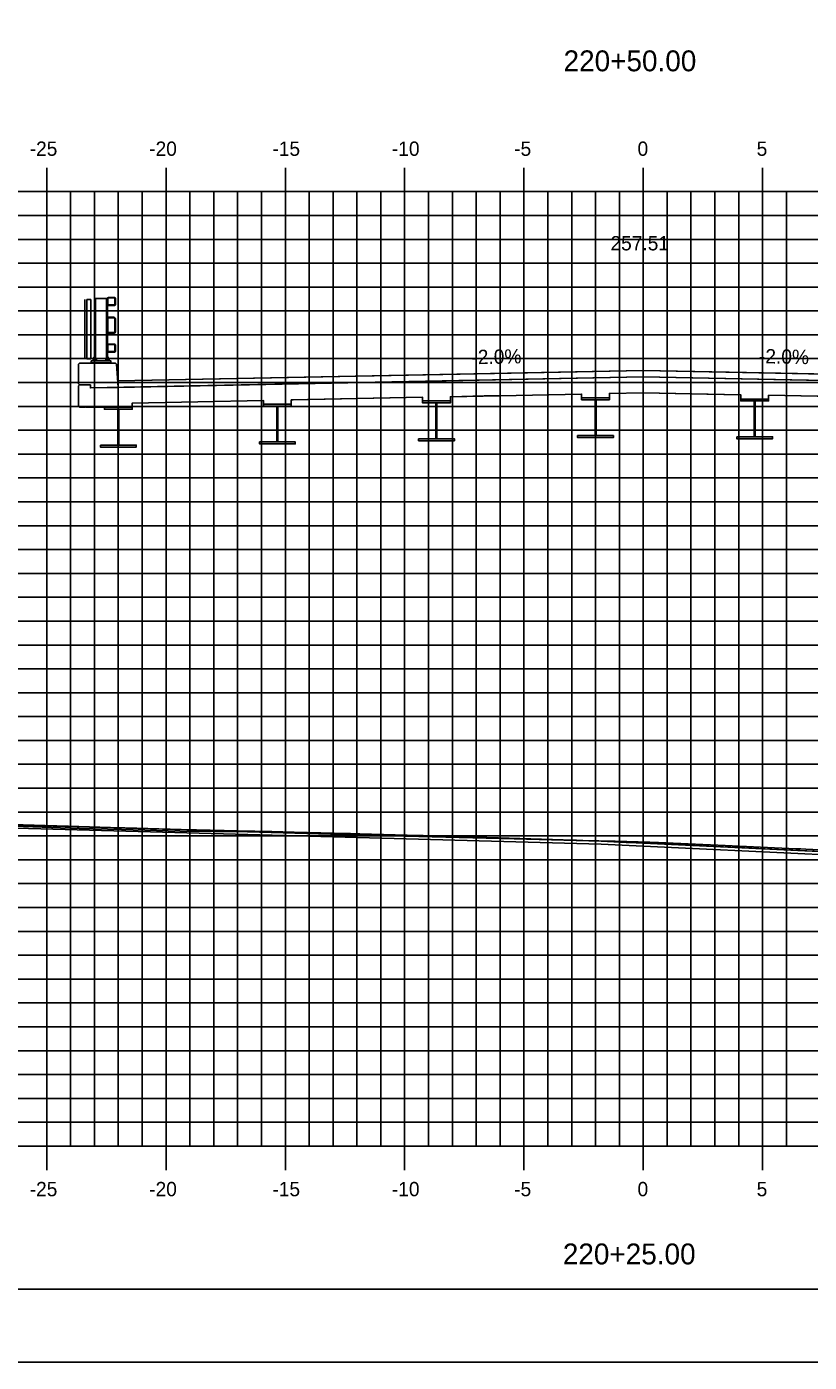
# Model space of a CAD drawing. Extents: x -22 to 1480, y -1511 to 8.
# Drawn here: x 700.4 to 733.2, y -184.5 to -128.6 of the extents above; entities that cross this region are included whole.
import ezdxf

# ---------------------------------------------------------------- set-up
doc = ezdxf.new("R2010")
doc.units = 0
for name, color, linetype in [('ANNOTATION', 7, 'Continuous'), ('BORDER', 7, 'Continuous'), ('D_Bridge_Deck', 7, 'Continuous'), ('D_Bridge_Railing', 7, 'Continuous'), ('D_Bridge_Superstructure', 7, 'Continuous'), ('D_Bridge_Superstructure_Slab', 7, 'Continuous'), ('D_Roadway_Centerline', 7, 'Continuous'), ('D_Roadway_Centerline_Text', 7, 'Continuous'), ('D_Roadway_Edge_TW', 7, 'Continuous'), ('H_V ANNOTATION', 7, 'Continuous'), ('MAJOR', 7, 'Continuous'), ('MINOR', 7, 'Continuous'), ('PLOT BOUNDARY', 7, 'Continuous'), ('S_Roadway_Centerline', 7, 'Continuous')]:
    doc.layers.add(name, color=color, linetype=linetype)

msp = doc.modelspace()

# ---------------------------------------------------------------- linework, layer by layer
at = {"layer": 'BORDER'}
msp.add_line((651.209, -181.466), (811.209, -181.466), dxfattribs=at)
at = {"layer": 'D_Bridge_Deck'}
for p, q in [((703.042, -143.569), (702.584, -143.569)), ((703.042, -143.694), (703.042, -143.569))]:
    msp.add_line(p, q, dxfattribs=at)
for points in [[(702.584, -143.569), (702.542, -143.527), (702.542, -142.691), (702.584, -142.65), (704.084, -142.65), (704.129, -142.691), (704.209, -143.67)], [(702.834, -144.504), (703.542, -144.504)]]:
    msp.add_lwpolyline(points, dxfattribs=at)
at = {"layer": 'D_Bridge_Railing'}
for p, q in [((703.792, -139.9), (704.042, -139.9)), ((703.792, -139.92), (704.042, -139.92)), ((702.886, -139.983), (702.886, -142.474)), ((703.052, -139.983), (702.886, -139.983)), ((703.052, -139.983), (703.052, -142.474)), ((703.257, -139.941), (703.257, -142.473)), ((703.712, -139.941), (703.712, -142.473)), ((703.751, -140.191), (703.751, -139.941)), ((703.771, -140.191), (703.771, -139.941)), ((704.042, -140.212), (703.792, -140.212)), ((704.042, -140.233), (703.792, -140.233)), ((704.063, -139.941), (704.063, -140.191)), ((704.084, -139.941), (704.084, -140.191)), ((703.751, -140.785), (703.751, -141.348)), ((703.776, -140.785), (703.776, -141.348)), ((704.032, -140.733), (703.802, -140.733)), ((704.032, -140.759), (703.802, -140.759)), ((704.058, -141.348), (704.058, -140.785)), ((704.084, -141.348), (704.084, -140.785)), ((703.802, -141.374), (704.032, -141.374)), ((703.802, -141.4), (704.032, -141.4)), ((703.751, -142.15), (703.751, -141.9)), ((703.771, -142.15), (703.771, -141.9)), ((703.792, -141.858), (704.042, -141.858)), ((703.792, -141.879), (704.042, -141.879)), ((704.063, -141.9), (704.063, -142.15)), ((704.084, -141.9), (704.084, -142.15)), ((703.052, -142.474), (702.886, -142.474)), ((703.183, -142.399), (703.256, -142.399)), ((703.183, -142.408), (703.256, -142.408)), ((703.183, -142.416), (703.256, -142.416)), ((703.183, -142.424), (703.256, -142.424)), ((703.183, -142.433), (703.256, -142.433)), ((703.183, -142.441), (703.256, -142.441)), ((703.183, -142.449), (703.256, -142.449)), ((703.183, -142.457), (703.256, -142.457)), ((703.183, -142.466), (703.256, -142.466)), ((703.185, -142.481), (703.185, -142.537)), ((703.201, -142.404), (703.237, -142.404)), ((703.201, -142.412), (703.237, -142.412)), ((703.201, -142.42), (703.237, -142.42)), ((703.201, -142.428), (703.237, -142.428)), ((703.201, -142.437), (703.237, -142.437)), ((703.201, -142.445), (703.237, -142.445)), ((703.201, -142.453), (703.237, -142.453)), ((703.201, -142.462), (703.237, -142.462)), ((703.201, -142.47), (703.237, -142.47)), ((703.254, -142.481), (703.254, -142.537)), ((703.714, -142.399), (703.787, -142.399)), ((703.714, -142.408), (703.787, -142.408)), ((703.714, -142.416), (703.787, -142.416)), ((703.714, -142.424), (703.787, -142.424)), ((703.714, -142.433), (703.787, -142.433)), ((703.714, -142.441), (703.787, -142.441)), ((703.714, -142.449), (703.787, -142.449)), ((703.714, -142.457), (703.787, -142.457)), ((703.714, -142.466), (703.787, -142.466)), ((703.716, -142.481), (703.716, -142.537)), ((703.732, -142.404), (703.769, -142.404)), ((703.732, -142.412), (703.769, -142.412)), ((703.732, -142.42), (703.769, -142.42)), ((703.732, -142.428), (703.769, -142.428)), ((703.732, -142.437), (703.769, -142.437)), ((703.732, -142.445), (703.769, -142.445)), ((703.732, -142.453), (703.769, -142.453)), ((703.732, -142.462), (703.769, -142.462)), ((703.732, -142.47), (703.769, -142.47)), ((703.785, -142.481), (703.785, -142.537)), ((704.042, -142.17), (703.792, -142.17)), ((704.042, -142.191), (703.792, -142.191))]:
    msp.add_line(p, q, dxfattribs=at)
for points in [[(702.802, -139.983), (702.802, -142.474)], [(703.219, -142.391), (703.219, -139.941), (703.751, -139.941), (703.751, -142.391)], [(703.183, -142.473), (703.183, -142.399), (703.191, -142.391), (703.247, -142.391), (703.256, -142.399), (703.256, -142.473)], [(703.714, -142.473), (703.714, -142.399), (703.722, -142.391), (703.779, -142.391), (703.787, -142.399), (703.787, -142.473)]]:
    msp.add_lwpolyline(points, dxfattribs=at)
for points in [[(703.075, -142.558), (703.895, -142.558), (703.895, -142.64), (703.075, -142.64)], [(703.075, -142.64), (703.895, -142.64), (703.895, -142.65), (703.075, -142.65)], [(703.146, -142.558), (703.292, -142.558), (703.292, -142.545), (703.146, -142.545)], [(703.15, -142.481), (703.164, -142.473), (703.274, -142.473), (703.288, -142.481), (703.288, -142.537), (703.274, -142.545), (703.164, -142.545), (703.15, -142.537)], [(703.678, -142.558), (703.823, -142.558), (703.823, -142.545), (703.678, -142.545)], [(703.682, -142.481), (703.695, -142.473), (703.806, -142.473), (703.819, -142.481), (703.819, -142.537), (703.806, -142.545), (703.695, -142.545), (703.682, -142.537)]]:
    msp.add_lwpolyline(points, close=True, dxfattribs=at)
for centre, radius, start, end in [((703.792, -139.941), 0.0417, 90, 180), ((703.792, -139.941), 0.0208, 90, 180), ((704.042, -139.941), 0.0417, 0, 90), ((704.042, -139.941), 0.0208, 0, 90), ((703.792, -140.191), 0.0417, 180, 270), ((703.792, -140.191), 0.0208, 180, 270), ((704.042, -140.191), 0.0417, 270, 0), ((704.042, -140.191), 0.0208, 270, 0), ((703.802, -140.785), 0.052, 90, 180), ((703.802, -140.785), 0.026, 90, 180), ((704.032, -140.785), 0.052, 0, 90), ((704.032, -140.785), 0.026, 0, 90), ((703.802, -141.348), 0.052, 180, 270), ((703.802, -141.348), 0.026, 180, 270), ((704.032, -141.348), 0.052, 270, 0), ((704.032, -141.348), 0.026, 270, 0), ((703.792, -141.9), 0.0417, 90, 180), ((703.792, -142.15), 0.0417, 180, 270), ((703.792, -141.9), 0.0208, 90, 180), ((703.792, -142.15), 0.0208, 180, 270), ((704.042, -141.9), 0.0417, 0, 90), ((704.042, -141.9), 0.0208, 0, 90), ((704.042, -142.15), 0.0417, 270, 0), ((704.042, -142.15), 0.0208, 270, 0), ((703.168, -142.506), 0.0302, 55.4339, 120), ((703.168, -142.512), 0.0302, 240, 304.5661), ((703.219, -142.59), 0.114, 72.412, 107.588), ((703.219, -142.428), 0.114, 252.412, 287.588), ((703.271, -142.506), 0.0302, 60, 124.5661), ((703.271, -142.512), 0.0302, 235.4339, 300), ((703.699, -142.506), 0.0302, 55.4339, 120), ((703.699, -142.512), 0.0302, 240, 304.5661), ((703.751, -142.59), 0.114, 72.412, 107.588), ((703.751, -142.428), 0.114, 252.412, 287.588), ((703.802, -142.506), 0.0302, 60, 124.5661), ((703.802, -142.512), 0.0302, 235.4339, 300)]:
    msp.add_arc(centre, radius, start, end, dxfattribs=at)
at = {"layer": 'D_Bridge_Superstructure'}
for p, q in [((711.459, -144.37), (710.292, -144.37)), ((710.292, -144.37), (710.292, -144.454)), ((711.459, -144.454), (711.459, -144.37)), ((718.126, -144.237), (716.959, -144.237)), ((716.959, -144.237), (716.959, -144.32)), ((717.563, -144.32), (717.522, -144.32)), ((717.563, -144.32), (717.522, -144.32)), ((717.563, -144.32), (718.126, -144.32)), ((718.126, -144.32), (718.126, -144.237)), ((724.792, -144.104), (723.626, -144.104)), ((723.626, -144.104), (723.626, -144.187)), ((724.23, -144.187), (724.188, -144.187)), ((724.23, -144.187), (724.188, -144.187)), ((724.23, -144.187), (724.792, -144.187)), ((724.792, -144.187), (724.792, -144.104)), ((731.459, -144.157), (730.292, -144.157)), ((730.292, -144.157), (730.292, -144.24)), ((730.897, -144.24), (730.855, -144.24)), ((730.897, -144.24), (730.855, -144.24)), ((730.897, -144.24), (731.459, -144.24)), ((731.459, -144.24), (731.459, -144.157)), ((704.792, -144.504), (703.626, -144.504)), ((703.626, -144.504), (703.626, -144.587)), ((704.23, -144.587), (704.188, -144.587)), ((704.23, -144.587), (704.188, -144.587)), ((704.23, -144.587), (704.792, -144.587)), ((704.792, -144.587), (704.792, -144.504)), ((710.897, -144.454), (710.855, -144.454)), ((710.897, -144.454), (710.855, -144.454)), ((710.897, -144.454), (711.459, -144.454)), ((710.855, -145.954), (710.126, -145.954)), ((710.126, -145.954), (710.126, -146.037)), ((710.855, -145.954), (710.126, -145.954)), ((710.897, -145.954), (710.855, -145.954)), ((710.897, -145.954), (710.855, -145.954)), ((717.522, -145.82), (716.792, -145.82)), ((716.792, -145.82), (716.792, -145.904)), ((717.522, -145.82), (716.792, -145.82)), ((717.563, -145.82), (717.522, -145.82)), ((717.563, -145.82), (717.522, -145.82)), ((724.188, -145.687), (723.459, -145.687)), ((723.459, -145.687), (723.459, -145.77)), ((724.188, -145.687), (723.459, -145.687)), ((724.23, -145.687), (724.188, -145.687)), ((724.23, -145.687), (724.188, -145.687)), ((730.855, -145.74), (730.126, -145.74)), ((730.126, -145.74), (730.126, -145.824)), ((730.855, -145.74), (730.126, -145.74)), ((730.897, -145.74), (730.855, -145.74)), ((730.897, -145.74), (730.855, -145.74)), ((704.188, -146.087), (703.459, -146.087)), ((703.459, -146.087), (703.459, -146.17)), ((704.188, -146.087), (703.459, -146.087)), ((704.23, -146.087), (704.188, -146.087)), ((704.23, -146.087), (704.188, -146.087))]:
    msp.add_line(p, q, dxfattribs=at)
for points in [[(710.292, -144.37), (711.459, -144.37), (711.459, -144.454), (710.292, -144.454)], [(716.959, -144.237), (718.126, -144.237), (718.126, -144.32), (716.959, -144.32)], [(717.522, -144.32), (717.563, -144.32), (717.563, -145.82), (717.522, -145.82)], [(723.626, -144.104), (724.792, -144.104), (724.792, -144.187), (723.626, -144.187)], [(724.188, -144.187), (724.23, -144.187), (724.23, -145.687), (724.188, -145.687)], [(730.292, -144.157), (731.459, -144.157), (731.459, -144.24), (730.292, -144.24)], [(730.855, -144.24), (730.897, -144.24), (730.897, -145.74), (730.855, -145.74)], [(703.626, -144.504), (704.792, -144.504), (704.792, -144.587), (703.626, -144.587)], [(704.188, -144.587), (704.23, -144.587), (704.23, -146.087), (704.188, -146.087)], [(710.855, -144.454), (710.897, -144.454), (710.897, -145.954), (710.855, -145.954)], [(710.126, -145.954), (711.626, -145.954), (711.626, -146.037), (710.126, -146.037)], [(716.792, -145.82), (718.292, -145.82), (718.292, -145.904), (716.792, -145.904)], [(723.459, -145.687), (724.959, -145.687), (724.959, -145.77), (723.459, -145.77)], [(730.126, -145.74), (731.626, -145.74), (731.626, -145.824), (730.126, -145.824)], [(703.459, -146.087), (704.959, -146.087), (704.959, -146.17), (703.459, -146.17)]]:
    msp.add_lwpolyline(points, close=True, dxfattribs=at)
for points in [[(710.897, -144.454), (711.459, -144.454), (711.459, -144.37), (710.292, -144.37), (710.292, -144.454), (710.855, -144.454), (710.897, -144.454)], [(717.563, -144.32), (718.126, -144.32), (718.126, -144.237), (716.959, -144.237), (716.959, -144.32), (717.522, -144.32), (717.563, -144.32)], [(716.959, -144.32), (717.522, -144.32), (717.563, -144.32)], [(717.522, -144.32), (717.522, -145.82), (717.563, -145.82), (717.563, -144.32)], [(717.522, -144.32), (717.522, -145.82), (717.563, -145.82), (717.563, -144.32)], [(724.23, -144.187), (724.792, -144.187), (724.792, -144.104), (723.626, -144.104), (723.626, -144.187), (724.188, -144.187), (724.23, -144.187)], [(723.626, -144.187), (724.188, -144.187), (724.23, -144.187)], [(724.188, -144.187), (724.188, -145.687), (724.23, -145.687), (724.23, -144.187)], [(724.188, -144.187), (724.188, -145.687), (724.23, -145.687), (724.23, -144.187)], [(730.897, -144.24), (731.459, -144.24), (731.459, -144.157), (730.292, -144.157), (730.292, -144.24), (730.855, -144.24), (730.897, -144.24)], [(730.292, -144.24), (730.855, -144.24), (730.897, -144.24)], [(730.855, -144.24), (730.855, -145.74), (730.897, -145.74), (730.897, -144.24)], [(730.855, -144.24), (730.855, -145.74), (730.897, -145.74), (730.897, -144.24)], [(704.23, -144.587), (704.792, -144.587), (704.792, -144.504), (703.626, -144.504), (703.626, -144.587), (704.188, -144.587), (704.23, -144.587)], [(703.626, -144.587), (704.188, -144.587), (704.23, -144.587)], [(704.188, -144.587), (704.188, -146.087), (704.23, -146.087), (704.23, -144.587)], [(704.188, -144.587), (704.188, -146.087), (704.23, -146.087), (704.23, -144.587)], [(710.292, -144.454), (710.855, -144.454), (710.897, -144.454)], [(710.855, -144.454), (710.855, -145.954), (710.897, -145.954), (710.897, -144.454)], [(710.855, -144.454), (710.855, -145.954), (710.897, -145.954), (710.897, -144.454)], [(710.126, -145.954), (710.126, -146.037), (711.626, -146.037), (711.626, -145.954), (710.897, -145.954)], [(710.126, -146.037), (711.626, -146.037), (711.626, -145.954), (710.897, -145.954)], [(716.792, -145.82), (716.792, -145.904), (718.292, -145.904), (718.292, -145.82), (717.563, -145.82)], [(716.792, -145.904), (718.292, -145.904), (718.292, -145.82), (717.563, -145.82)], [(723.459, -145.687), (723.459, -145.77), (724.959, -145.77), (724.959, -145.687), (724.23, -145.687)], [(723.459, -145.77), (724.959, -145.77), (724.959, -145.687), (724.23, -145.687)], [(730.126, -145.74), (730.126, -145.824), (731.626, -145.824), (731.626, -145.74), (730.897, -145.74)], [(730.126, -145.824), (731.626, -145.824), (731.626, -145.74), (730.897, -145.74)], [(703.459, -146.087), (703.459, -146.17), (704.959, -146.17), (704.959, -146.087), (704.23, -146.087)], [(703.459, -146.17), (704.959, -146.17), (704.959, -146.087), (704.23, -146.087)]]:
    msp.add_lwpolyline(points, dxfattribs=at)
at = {"layer": 'D_Bridge_Superstructure_Slab'}
for p, q in [((711.542, -144.19), (711.542, -144.19)), ((726.209, -143.897), (726.209, -143.897))]:
    msp.add_line(p, q, dxfattribs=at)
for points in [[(704.209, -143.67), (704.129, -142.691), (704.084, -142.65), (702.584, -142.65), (702.542, -142.691), (702.542, -143.527), (702.584, -143.569), (703.042, -143.569), (703.042, -143.694)], [(744.231, -143.32), (744.209, -143.59), (726.209, -143.23), (704.209, -143.67), (704.187, -143.4), (726.209, -142.96)]]:
    msp.add_lwpolyline(points, close=True, dxfattribs=at)
for points in [[(745.376, -143.614), (726.209, -143.23), (703.042, -143.694), (703.042, -143.569), (702.584, -143.569), (702.542, -143.61), (702.542, -144.462), (702.584, -144.504), (702.792, -144.504), (702.792, -144.462), (702.834, -144.504), (704.792, -144.504), (704.792, -144.325), (710.292, -144.215), (710.292, -144.37), (711.459, -144.37), (711.459, -144.192), (711.542, -144.19), (712.876, -144.164), (716.959, -144.082), (716.959, -144.237), (718.126, -144.237), (718.126, -144.059), (719.542, -144.03), (720.876, -144.004), (723.626, -143.949), (723.626, -144.104), (724.792, -144.104), (724.792, -143.925), (726.209, -143.897), (727.542, -143.924), (728.876, -143.95), (730.292, -143.979), (730.292, -144.157), (731.459, -144.157), (731.459, -144.002), (735.542, -144.084)], [(745.376, -143.614), (726.209, -143.23), (703.042, -143.694)], [(702.792, -144.504), (702.584, -144.504), (702.542, -144.462), (702.542, -143.61), (702.584, -143.569)], [(703.542, -144.504), (704.792, -144.504), (704.792, -144.325)], [(710.292, -144.215), (704.792, -144.325)], [(711.459, -144.192), (711.459, -144.37), (710.292, -144.37), (710.292, -144.215)], [(716.959, -144.082), (711.459, -144.192)], [(718.126, -144.059), (718.126, -144.237), (716.959, -144.237), (716.959, -144.082)], [(723.626, -143.949), (718.126, -144.059)], [(724.792, -143.925), (724.792, -144.104), (723.626, -144.104), (723.626, -143.949)], [(730.292, -143.979), (726.209, -143.897), (724.792, -143.925)], [(730.292, -143.979), (730.292, -144.157), (731.459, -144.157), (731.459, -144.002)], [(736.959, -144.112), (731.459, -144.002)], [(702.792, -144.504), (702.792, -144.462), (702.834, -144.504)], [(702.792, -144.504), (702.792, -144.462), (702.834, -144.504)]]:
    msp.add_lwpolyline(points, dxfattribs=at)
at = {"layer": 'D_Roadway_Centerline'}
for points in [[(704.187, -143.4), (709.209, -143.3), (714.209, -143.2), (719.969, -143.084), (726.209, -142.96), (731.969, -143.075), (738.209, -143.2), (741.209, -143.26), (744.231, -143.32)], [(699.056, -162.03), (702.574, -162.162), (704.342, -162.204), (706.788, -162.263), (709.629, -162.295), (713.097, -162.387), (714.915, -162.437), (716.236, -162.471), (720.201, -162.576), (720.794, -162.589), (724.445, -162.689), (725.488, -162.737), (725.67, -162.746), (730.774, -162.983), (731.88, -163.036), (736.06, -163.231)]]:
    msp.add_lwpolyline(points, dxfattribs=at)
at = {"layer": 'D_Roadway_Edge_TW'}
msp.add_lwpolyline([(759.781, -164.493), (759.781, -164.368), (724.445, -162.689), (691.239, -161.774), (691.239, -161.899), (724.445, -162.814)], close=True, dxfattribs=at)
at = {"layer": 'MAJOR'}
for p, q in [((701.209, -134.464), (701.209, -135.466)), ((706.209, -134.464), (706.209, -135.466)), ((711.209, -134.464), (711.209, -135.466)), ((716.209, -134.464), (716.209, -135.466)), ((721.209, -134.464), (721.209, -135.466)), ((726.209, -134.464), (726.209, -135.466)), ((731.209, -134.464), (731.209, -135.466)), ((656.209, -135.466), (796.209, -135.466)), ((656.209, -135.466), (796.209, -135.466)), ((701.209, -175.466), (701.209, -135.466)), ((706.209, -175.466), (706.209, -135.466)), ((711.209, -175.466), (711.209, -135.466)), ((716.209, -175.466), (716.209, -135.466)), ((721.209, -175.466), (721.209, -135.466)), ((726.209, -175.466), (726.209, -135.466)), ((731.209, -175.466), (731.209, -135.466)), ((656.209, -140.466), (796.209, -140.466)), ((656.209, -145.466), (796.209, -145.466)), ((656.209, -150.466), (796.209, -150.466)), ((656.209, -155.466), (796.209, -155.466)), ((656.209, -160.466), (796.209, -160.466)), ((656.209, -165.466), (796.209, -165.466)), ((656.209, -170.466), (796.209, -170.466)), ((656.209, -175.466), (796.209, -175.466)), ((656.209, -175.466), (796.209, -175.466)), ((701.209, -176.468), (701.209, -175.466)), ((706.209, -176.468), (706.209, -175.466)), ((711.209, -176.468), (711.209, -175.466)), ((716.209, -176.468), (716.209, -175.466)), ((721.209, -176.468), (721.209, -175.466)), ((726.209, -176.468), (726.209, -175.466)), ((731.209, -176.468), (731.209, -175.466))]:
    msp.add_line(p, q, dxfattribs=at)
at = {"layer": 'MINOR'}
for p, q in [((702.209, -175.466), (702.209, -135.466)), ((703.209, -175.466), (703.209, -135.466)), ((704.209, -175.466), (704.209, -135.466)), ((705.209, -175.466), (705.209, -135.466)), ((707.209, -175.466), (707.209, -135.466)), ((708.209, -175.466), (708.209, -135.466)), ((709.209, -175.466), (709.209, -135.466)), ((710.209, -175.466), (710.209, -135.466)), ((712.209, -175.466), (712.209, -135.466)), ((713.209, -175.466), (713.209, -135.466)), ((714.209, -175.466), (714.209, -135.466)), ((715.209, -175.466), (715.209, -135.466)), ((717.209, -175.466), (717.209, -135.466)), ((718.209, -175.466), (718.209, -135.466)), ((719.209, -175.466), (719.209, -135.466)), ((720.209, -175.466), (720.209, -135.466)), ((722.209, -175.466), (722.209, -135.466)), ((723.209, -175.466), (723.209, -135.466)), ((724.209, -175.466), (724.209, -135.466)), ((725.209, -175.466), (725.209, -135.466)), ((727.209, -175.466), (727.209, -135.466)), ((728.209, -175.466), (728.209, -135.466)), ((729.209, -175.466), (729.209, -135.466)), ((730.209, -175.466), (730.209, -135.466)), ((732.209, -175.466), (732.209, -135.466)), ((656.209, -136.466), (796.209, -136.466)), ((656.209, -137.466), (796.209, -137.466)), ((656.209, -138.466), (796.209, -138.466)), ((656.209, -139.466), (796.209, -139.466)), ((656.209, -141.466), (796.209, -141.466)), ((656.209, -142.466), (796.209, -142.466)), ((656.209, -143.466), (796.209, -143.466)), ((656.209, -144.466), (796.209, -144.466)), ((656.209, -146.466), (796.209, -146.466)), ((656.209, -147.466), (796.209, -147.466)), ((656.209, -148.466), (796.209, -148.466)), ((656.209, -149.466), (796.209, -149.466)), ((656.209, -151.466), (796.209, -151.466)), ((656.209, -152.466), (796.209, -152.466)), ((656.209, -153.466), (796.209, -153.466)), ((656.209, -154.466), (796.209, -154.466)), ((656.209, -156.466), (796.209, -156.466)), ((656.209, -157.466), (796.209, -157.466)), ((656.209, -158.466), (796.209, -158.466)), ((656.209, -159.466), (796.209, -159.466)), ((656.209, -161.466), (796.209, -161.466)), ((656.209, -162.466), (796.209, -162.466)), ((656.209, -163.466), (796.209, -163.466)), ((656.209, -164.466), (796.209, -164.466)), ((656.209, -166.466), (796.209, -166.466)), ((656.209, -167.466), (796.209, -167.466)), ((656.209, -168.466), (796.209, -168.466)), ((656.209, -169.466), (796.209, -169.466)), ((656.209, -171.466), (796.209, -171.466)), ((656.209, -172.466), (796.209, -172.466)), ((656.209, -173.466), (796.209, -173.466)), ((656.209, -174.466), (796.209, -174.466))]:
    msp.add_line(p, q, dxfattribs=at)
at = {"layer": 'PLOT BOUNDARY'}
msp.add_lwpolyline([(643.116, -184.525), (813.116, -184.525), (813.116, -74.525), (643.116, -74.525)], close=True, dxfattribs=at)
at = {"layer": 'S_Roadway_Centerline'}
msp.add_lwpolyline([(699.754, -161.986), (701.147, -162.028), (702.119, -162.06), (704.313, -162.121), (704.484, -162.126), (704.988, -162.14), (706.849, -162.193), (707.48, -162.207), (709.214, -162.255), (710.647, -162.288), (711.58, -162.311), (713.814, -162.363), (713.945, -162.367), (714.331, -162.375), (716.31, -162.434), (716.981, -162.453), (718.675, -162.509), (720.147, -162.55), (721.04, -162.577), (723.313, -162.644), (723.405, -162.646), (723.675, -162.653), (725.03, -162.688), (726.48, -162.729), (726.847, -162.74), (729.644, -162.864), (732.605, -163.002), (732.808, -163.012), (733.019, -163.022), (735.973, -163.156)], dxfattribs=at)

# ---------------------------------------------------------------- texts
at = {"layer": 'ANNOTATION'}
for rotation, p in [(1.1458, (719.012, -142.703)), (358.8542, (731.052, -142.656))]:
    msp.add_text('-2.0%', height=0.6, rotation=rotation, dxfattribs=at).set_placement(p)
at = {"layer": 'D_Roadway_Centerline'}
for s, p in [('C', (724.44, -162.689)), ('L', (724.445, -162.696))]:
    msp.add_text(s, height=0.0146, dxfattribs=at).set_placement(p)
at = {"layer": 'D_Roadway_Centerline_Text'}
msp.add_text('257.51', height=0.6, dxfattribs=at).set_placement((724.833, -137.928))
at = {"layer": 'H_V ANNOTATION'}
for s, height, p in [('220+50.00', 0.875, (722.869, -130.423)), ('-25', 0.6, (700.494, -133.966)), ('-20', 0.6, (705.502, -133.966)), ('-15', 0.6, (710.666, -133.966)), ('-10', 0.6, (715.674, -133.966)), ('-5', 0.6, (720.799, -133.966)), ('0', 0.6, (725.968, -133.966)), ('5', 0.6, (730.96, -133.966)), ('-25', 0.6, (700.494, -177.566)), ('-20', 0.6, (705.502, -177.566)), ('-15', 0.6, (710.666, -177.566)), ('-10', 0.6, (715.674, -177.566)), ('-5', 0.6, (720.799, -177.566)), ('0', 0.6, (725.968, -177.566)), ('5', 0.6, (730.96, -177.566)), ('220+25.00', 0.875, (722.838, -180.423))]:
    msp.add_text(s, height=height, dxfattribs=at).set_placement(p)

doc.saveas('drawing.dxf')
